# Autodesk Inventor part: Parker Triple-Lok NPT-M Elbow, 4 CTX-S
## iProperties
Shininess: 27.0
Length Units: 11272
Angle Units: 11279
Time Units: 11290
Mass Units: 11286
Length Display Precision: 3
Angle Display Precision: 2
Category: Hydraulics
Created: 2001-03
Part Number: Parker Triple-Lok NPT-M Elbow, 4 CTX-S
Material: Stainless Steel, Austenitic
Catalog Web Link: http://www.aeroquip.com
Description: Parker Triple-Lok NPT-M Elbow, 4 CTX-S
Document SubType Name: Modeling
Designer: QBZ
Density: 7.86
Volumn: 11.938033425281926
Area: 60.34729061233818
PropertySet Name: Model Information
Control State: 0
Master: False
Checked Out: False
Last Check In By: Charles Bliss
Last Check In Date: 2003-09-27
Title: JIC Elbow 90 deg Union
Subject: Hydraulic Adapters
Author: QBZ
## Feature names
1. Body1 [Extrusion]
2. Body2 [Extrusion]
3. Revolution1
4. JIC 1 [Revolution]
5. JIC1 id
6. Fillet1
7. Extrusion3
8. Hole2
